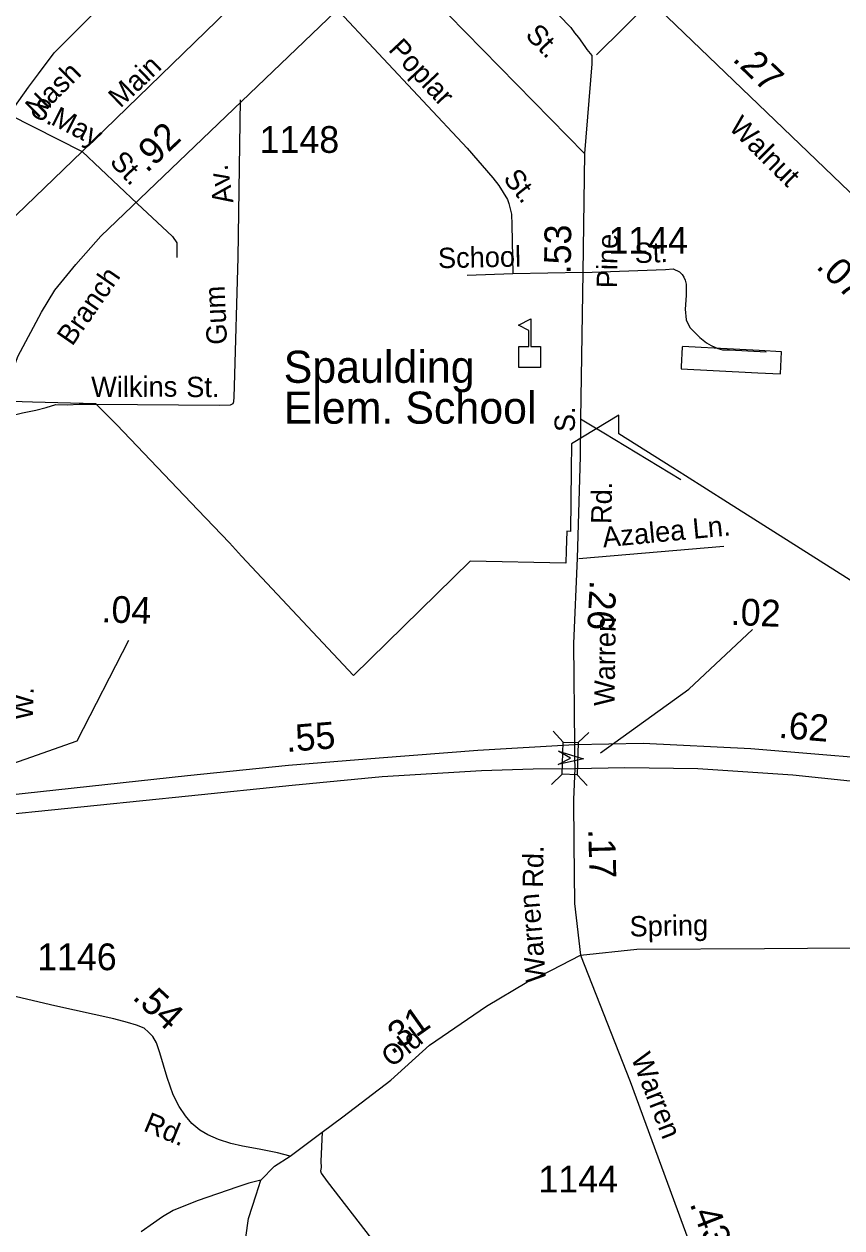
# Model space of a CAD drawing. Extents: x 2220236 to 2384410, y 720751 to 894131.
# Drawn here: x 2261352 to 2265175, y 793300 to 798927 of the extents above; entities that cross this region are included whole.
import ezdxf

# ---------------------------------------------------------------- set-up
doc = ezdxf.new("R2010")
doc.units = 0
doc.layers.add('Default', color=7, linetype='Continuous')

msp = doc.modelspace()

# ---------------------------------------------------------------- linework, layer by layer
at = {"layer": 'Default'}
for p, q in [((2263064.6, 799247.1), (2263970.8, 798322)), ((2264027, 798783.1), (2264281, 799034.6)), ((2261623.6, 798331.6), (2262306.4, 798993.6)), ((2261282.2, 798505), (2261623.6, 798331.6)), ((2260978.6, 797711.9), (2261623.6, 798331.6)), ((2261623.6, 798331.6), (2261880, 798088.5)), ((2263964.1, 797766.1), (2263636.3, 797759.1)), ((2263636.3, 797759.1), (2263422.6, 797751.1)), ((2263944.6, 796428.7), (2264622.4, 796486.6)), ((2263872.2, 795571.5), (2263825.1, 795621.9)), ((2263941.2, 795569.1), (2263991.6, 795616.2)), ((2263816.4, 795373.3), (2263866.8, 795420.4)), ((2263984.5, 795367.7), (2263937.4, 795418.1))]:
    msp.add_line(p, q, dxfattribs=at)
for points in [[(2261282.2, 798505), (2261372.2, 798632.6), (2261418.7, 798694.3), (2261492.5, 798791.9), (2262026.6, 799326.8), (2262203, 799493.9), (2262803.1, 800062.3)], [(2261043.7, 795303.1), (2261082.5, 795400.1), (2261117.7, 795544.7), (2261123.2, 795686), (2261141.5, 795942), (2261171.7, 796557.5), (2261177.1, 796730.3), (2261181.4, 796970), (2261189, 797019.7), (2261217.8, 797094.2), (2261264.1, 797211.4), (2261322.7, 797372.6), (2261433.7, 797580.1), (2261494.8, 797682.7), (2261593.6, 797803.5), (2261710.7, 797935.4), (2262807.9, 798986.4), (2263047.3, 799222.8), (2263332, 799502.2)], [(2263332, 799502.2), (2263907.3, 798910.8), (2263924.6, 798885.6), (2263943.1, 798863.8), (2263973.4, 798822.2), (2263982.2, 798807.9), (2264005, 798780), (2264005, 798740.6), (2263970.8, 798322), (2263964.1, 797766.1), (2263952.6, 797082.4), (2263950.4, 796905.8), (2263936.7, 796431), (2263920.1, 796032.4), (2263924.2, 795558.8)], [(2262801, 799010.6), (2263422.9, 798347), (2263542.2, 798208.1), (2263570.4, 798172.4), (2263611, 798106.7), (2263617.3, 798088.8), (2263629.6, 798039), (2263632.2, 797988.9), (2263636.3, 797759.1)], [(2266964.1, 795660.4), (2266371.3, 796873.2), (2266310.4, 796972.7), (2266269.7, 797046.3), (2266154.2, 797215), (2266099.6, 797280.5), (2266012.7, 797371.7), (2265867.5, 797512.3), (2264281, 799034.6)], [(2261216.5, 797086.6), (2261262, 797089), (2261344.4, 797109.3), (2261406, 797122.3), (2261455.6, 797135.3), (2261500.9, 797148.2), (2261555.1, 797147.9), (2261608.9, 797150.4), (2261691.6, 797150.8), (2262263.7, 797146.4), (2262316.2, 797147.3), (2262329.7, 797154.1), (2262331.7, 797162.7), (2262333.6, 797183), (2262335.5, 797234.6), (2262352.6, 797836.5), (2262363.3, 798572.8)], [(2261880, 798088.5), (2262045.4, 797934.2), (2262065.7, 797904.3), (2262066.3, 797836.4)], [(2263964.1, 797766.1), (2264349.7, 797779.8), (2264385.7, 797782.2), (2264415.8, 797768.4), (2264428, 797756.6), (2264436.1, 797744.6), (2264442.2, 797730.7), (2264446.4, 797710.8), (2264446.9, 797658.8), (2264441.4, 797594.7), (2264446, 797544.8), (2264464.2, 797509.1), (2264510, 797461.8), (2264540.9, 797437.7), (2264563, 797424.1), (2264595.1, 797410.4), (2264617.2, 797404.5), (2264649.2, 797404.9), (2264821.1, 797394.5)], [(2264782.2, 797297.1), (2264887.2, 797291.6), (2264892.8, 797395.5), (2264787.8, 797401), (2264578, 797412), (2264516.2, 797415.2), (2264431.5, 797419.7), (2264428, 797416.4), (2264423.5, 797326.8), (2264422.8, 797315.9), (2264572.8, 797308.1), (2264782.2, 797297.1)], [(2264782.2, 797297.1), (2264887.2, 797291.6), (2264892.8, 797395.5), (2264787.8, 797401), (2264578, 797412), (2264516.2, 797415.2), (2264431.5, 797419.7), (2264428, 797416.4), (2264423.5, 797326.8), (2264422.8, 797315.9), (2264572.8, 797308.1), (2264782.2, 797297.1)], [(2265365.2, 796231.4), (2264640, 796691.1), (2264443.8, 796815.4), (2264383.8, 796853.2), (2264131.2, 797012.1), (2264132, 797098.5), (2263910.5, 796964.9), (2263909.2, 796843.7), (2263906.5, 796555.3), (2263889, 796556.5), (2263886.2, 796466.2), (2263884.5, 796406.6), (2263436.8, 796416.2), (2262891.2, 795882.1), (2262368.8, 796439.7), (2262311.2, 796501.8), (2262164, 796656.9), (2261785.5, 797053.1), (2261687.5, 797152), (2261390.8, 797160.2), (2261293.8, 797162.9)], [(2265365.2, 796231.4), (2264640, 796691.1), (2264443.8, 796815.4), (2264383.8, 796853.2), (2264131.2, 797012.1), (2264132, 797098.5), (2263910.5, 796964.9), (2263909.2, 796843.7), (2263906.5, 796555.3), (2263889, 796556.5), (2263886.2, 796466.2), (2263884.5, 796406.6), (2263436.8, 796416.2), (2262891.2, 795882.1), (2262368.8, 796439.7), (2262311.2, 796501.8), (2262164, 796656.9), (2261785.5, 797053.1), (2261687.5, 797152), (2261390.8, 797160.2), (2261293.8, 797162.9)], [(2263952.6, 797082.4), (2264061.2, 797016.7), (2264421, 796799)], [(2264046.2, 795520.4), (2264458.6, 795818.6), (2264756.8, 796097.7)], [(2261111.8, 795406.2), (2261600.3, 795577.5), (2261841.4, 796047)], [(2263924.2, 795558.8), (2263473, 795531.8), (2263012, 795496.4), (2262588.1, 795462.2), (2262115.9, 795413.9), (2261271.7, 795321.8), (2261043.7, 795303.1)], [(2265772.7, 795458.7), (2265573.6, 795471), (2264748.1, 795539.4), (2264245, 795564.1), (2263924.2, 795558.8)], [(2263924.2, 795558.8), (2263924.2, 795495.3), (2263926, 795447.7)], [(2261013.7, 795209.7), (2261265.8, 795232.2), (2262120.7, 795319.5), (2262604.1, 795369), (2263025, 795410.3), (2263489.5, 795438.6), (2263731.2, 795445.7), (2263926, 795447.7)], [(2263926, 795447.7), (2263920.7, 795303.1), (2263921.6, 795098.6), (2263925.1, 794816.5), (2263953.3, 794574.9)], [(2263926, 795447.7), (2264159.2, 795451.6), (2264501.2, 795448.1), (2264945.7, 795418.6), (2265749.8, 795333.6), (2265775.9, 795330.8)], [(2262595.1, 793635.4), (2262744.4, 793748.5), (2262841.6, 793819.5), (2263065.9, 793991.6), (2263246.1, 794154.8), (2263512.7, 794336.9), (2263701.3, 794449.7), (2263817.6, 794504.4), (2263953.3, 794574.9)], [(2263953.3, 794574.9), (2264215.9, 794603.1), (2264813.3, 794606.6), (2265818.7, 794613.7), (2265933.3, 794613.7), (2266073.4, 794610.2), (2266161.5, 794594.3), (2266286.6, 794555.5), (2267037.4, 794296.3), (2267759.2, 794053.6)], [(2263953.3, 794574.9), (2264185.1, 793984.2), (2264752.8, 792435.6)], [(2262595.1, 793635.4), (2262537, 793651.8), (2262450.6, 793668.2), (2262373.1, 793683.1), (2262318, 793695.1), (2262259.8, 793714.5), (2262210.7, 793735.3), (2262173.4, 793757.7), (2262136.2, 793789), (2262106.4, 793824.8), (2262076.6, 793868), (2262048.3, 793923.2), (2262020, 794003.7), (2261985.7, 794119.2), (2261970.8, 794165.4), (2261952.9, 794195.3), (2261933.6, 794214.6), (2261912.7, 794234), (2261876.9, 794247.4), (2261835.2, 794260.9), (2261771.1, 794277.3), (2261495.5, 794339.1), (2260969.6, 794461.4)], [(2262744.4, 793748.5), (2262739.6, 793612.7), (2262740, 793582.7), (2262738, 793566.7), (2262740.2, 793556.7), (2262768.6, 793516.9), (2262975, 793248.9)], [(2262458.3, 793523), (2262522.3, 793589.3), (2262595.1, 793635.4)], [(2262458.3, 793523), (2262401.8, 793510.4), (2262350.4, 793492.5), (2262160.4, 793427.7), (2262048.2, 793382.2), (2261999.5, 793352.7), (2261956.9, 793323.3), (2261899.2, 793282.9)], [(2262263.6, 792365.9), (2262400.4, 793344.3), (2262435.9, 793455.3), (2262458.3, 793523)]]:
    msp.add_lwpolyline(points, dxfattribs=at)
for points in [[(2263664.5, 797322.3), (2263664.5, 797420.2), (2263710.5, 797420.2), (2263710.5, 797495.3), (2263663.5, 797519.5), (2263720.1, 797548.7), (2263720.1, 797420.2), (2263766.2, 797420.2), (2263766.2, 797322.3)], [(2263866.8, 795420.4), (2263871.9, 795571.5), (2263942.4, 795569.1), (2263937.4, 795418.1)], [(2263849.7, 795529.1), (2263966.4, 795493.5), (2263847.6, 795466), (2263905.4, 795495.6)]]:
    msp.add_lwpolyline(points, close=True, dxfattribs=at)

# ---------------------------------------------------------------- texts
for s, height, rotation, p in [('St.', 95, 314.3921, (2263690.2, 798871.5)), ('Poplar', 95, 313.1421, (2263050.6, 798804.7)), ('.27', 125, 316.1825, (2264658.6, 798758.9)), ('Nash', 95, 44.678, (2261414.5, 798482.8)), ('Main', 95, 43.7402, (2261801.8, 798530.8)), ('S.', 95, 331.8902, (2261374.4, 798506.2)), ('May', 95, 333.0292, (2261471.9, 798460.3)), ('Walnut', 95, 315.0274, (2264641.2, 798439.9)), ('.92', 125, 43.7708, (2261925.5, 798227.7)), ('St.', 95, 313.1868, (2261747.6, 798279.7)), ('Av.', 95, 99.0326, (2262330.7, 798093.7)), ('St.', 95, 308.3062, (2263587.6, 798203.5)), ('.53', 125, 89.3095, (2263906.9, 797756.8)), ('Pine', 95, 89.0364, (2264123, 797691.8)), ('School', 95, 1.2236, (2263287.3, 797785.7)), ('St.', 95, 2.0349, (2264207, 797809.3)), ('.07', 125, 316.1825, (2265049.7, 797789.8)), ('Branch', 95, 55.2379, (2261576.7, 797418)), ('Gum', 95, 92.4012, (2262300.7, 797430.3)), ('Wilkins', 95, 0.2703, (2261665.8, 797183.5)), ('St.', 95, 359.981, (2262109.9, 797183.5)), ('S.', 95, 89.299, (2263926.1, 797019.6)), ('Rd.', 95, 89.0364, (2264097, 796589.8)), ('Azalea Ln.', 95, 5.4447, (2264059.4, 796480.8)), ('.26', 125, 266.8627, (2263996.9, 796329.5)), ('.04', 125, 358.0246, (2261712.1, 796131.3)), ('.02', 125, 357.6141, (2264653, 796119.1)), ('Warren', 95, 89.0364, (2264111.2, 795739.2)), ('W.', 95, 88.1535, (2261392.1, 795672.8)), ('.62', 125, 355.2652, (2264876.1, 795591.5)), ('.55', 125, 4.6145, (2262579, 795524.2)), ('.17', 125, 271.6095, (2263988.7, 795164.8)), ('Rd.', 95, 89.0364, (2263776.9, 794889.6)), ('Warren', 95, 94.7497, (2263792.4, 794452.1)), ('Spring', 95, 1.1894, (2264183, 794662.1)), ('.54', 125, 317.1023, (2261853.6, 794374.3)), ('.31', 125, 35.3207, (2263070.6, 794108.3)), ('Old', 95, 38.1714, (2263069, 794047.4)), ('Warren', 95, 291.3119, (2264187.7, 794096.6)), ('Rd.', 95, 337.4769, (2261904.7, 793756.3)), ('.43', 125, 291.3119, (2264461.7, 793413.6))]:
    msp.add_text(s, height=height, rotation=rotation, dxfattribs=at).set_placement(p)
for s, height, p in [('1148', 125, (2262452.8, 798324.9)), ('1144', 125, (2264083.1, 797854)), ('Spaulding', 150, (2262565.3, 797250.2)), ('Elem. School', 150, (2262565.3, 797059.2)), ('1146', 125, (2261412.8, 794505)), ('1144', 125, (2263755.8, 793466.3))]:
    msp.add_text(s, height=height, dxfattribs=at).set_placement(p)

doc.saveas('drawing.dxf')
